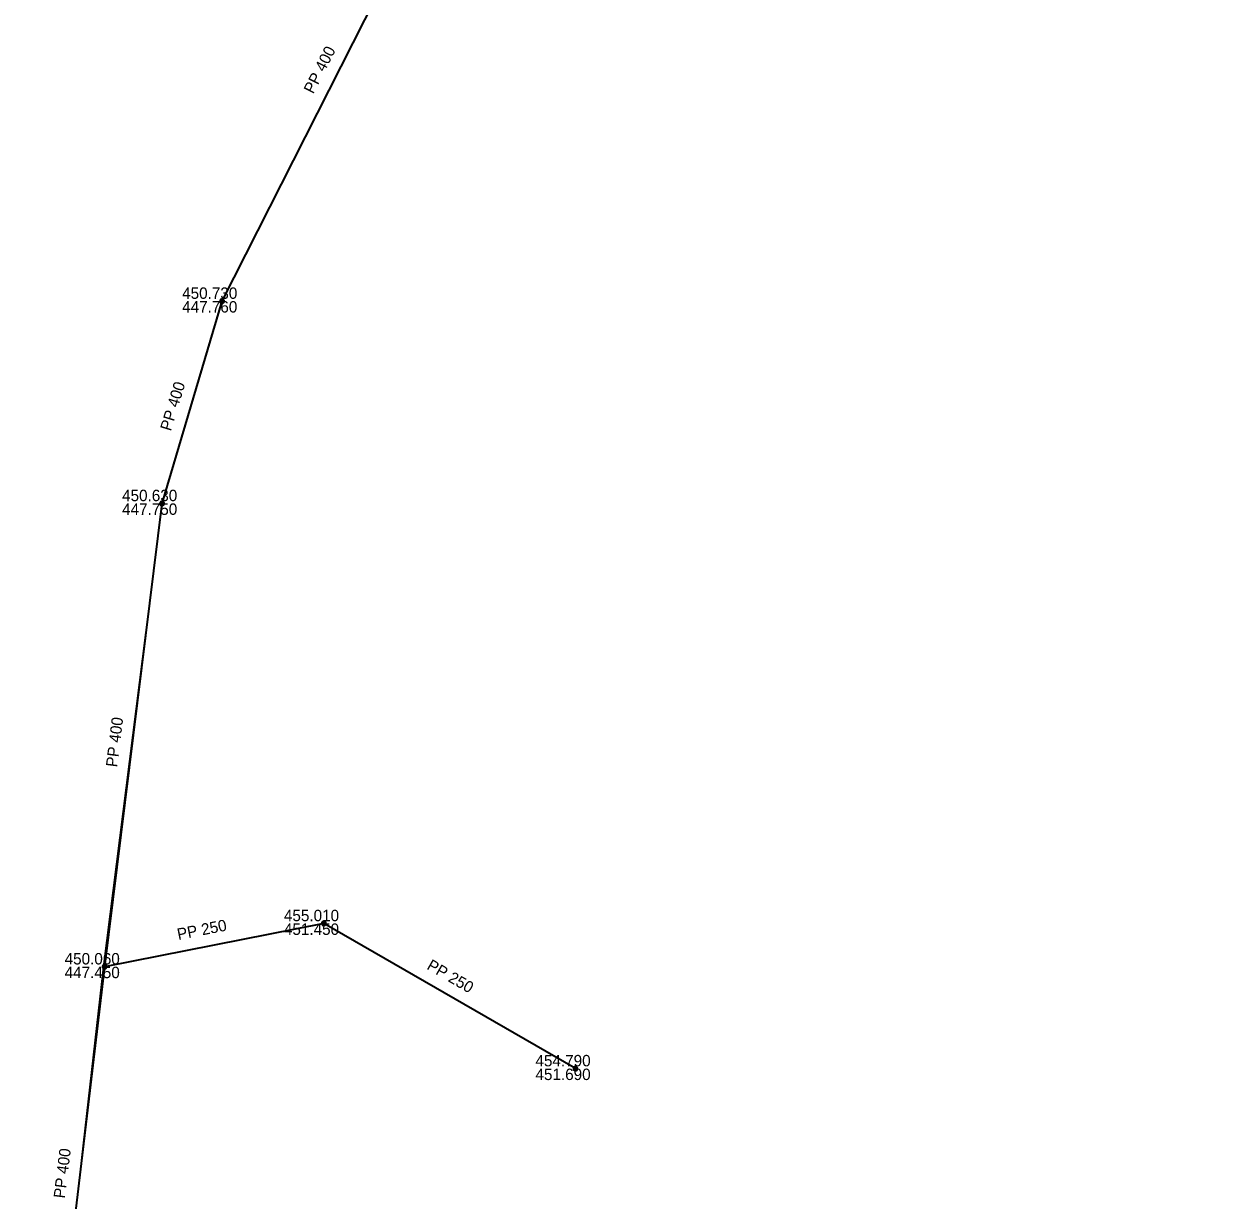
# Model space of a CAD drawing. Extents: x -873619 to -867639, y -1015082 to -1012326.
# Drawn here: x -873192.3 to -873076.9, y -1014089.5 to -1013976.1 of the extents above; entities that cross this region are included whole.
import ezdxf

# ---------------------------------------------------------------- set-up
doc = ezdxf.new("R2010")
doc.units = 0
doc.header["$LTSCALE"] = 0.44
for name, color, linetype, lineweight in [('1', 7, 'Continuous', 13), ('21', 7, 'Continuous', 35), ('3', 7, 'Continuous', 25), ('32', 7, 'Continuous', 13)]:
    doc.layers.add(name, color=color, linetype=linetype, lineweight=lineweight)

msp = doc.modelspace()

# ---------------------------------------------------------------- linework, layer by layer
at = {"layer": '21'}
for p, q in [((-873150.59, -1013958.19), (-873173.22, -1014002.85)), ((-873173.22, -1014002.85), (-873179.01, -1014022.35)), ((-873179.01, -1014022.35), (-873184.55, -1014067)), ((-873163.4, -1014062.83), (-873184.538, -1014067)), ((-873139.15, -1014076.82), (-873163.4, -1014062.83)), ((-873184.55, -1014067), (-873189.13, -1014105.45))]:
    msp.add_line(p, q, dxfattribs=at)
at = {"layer": '3'}
msp.add_lwpolyline([(-873209.421, -1014292.661), (-873208.998, -1014240.45), (-873211.448, -1014197.31), (-873215.58, -1014166.03), (-873205.44, -1014160.07), (-873195.92, -1014151.84), (-873190.998, -1014149.15), (-873189.02, -1014105.45), (-873184.64, -1014067), (-873178.998, -1014022.35), (-873173.208, -1014002.85), (-873150.578, -1013958.19), (-873123.56, -1013906.71), (-873116.49, -1013857.17), (-873096.298, -1013812.05), (-873076.908, -1013772.84), (-873099.08, -1013724.68), (-873112.568, -1013694.19), (-873154.458, -1013666.63), (-873180.788, -1013644.59), (-873224.641, -1013607.538), (-873251.958, -1013559.37), (-873281.448, -1013506.61), (-873307.717, -1013457.772)], dxfattribs=at)
at = {"layer": '32'}
for points in [[(-873172.978, -1014002.85), (-873172.985, -1014002.798), (-873173.002, -1014002.748), (-873173.031, -1014002.704), (-873173.068, -1014002.667), (-873173.113, -1014002.64), (-873173.163, -1014002.623), (-873173.216, -1014002.619), (-873173.267, -1014002.626), (-873173.316, -1014002.645), (-873173.36, -1014002.674), (-873173.396, -1014002.713), (-873173.422, -1014002.758), (-873173.438, -1014002.809), (-873173.441, -1014002.861), (-873173.433, -1014002.913), (-873173.413, -1014002.962), (-873173.382, -1014003.005), (-873173.343, -1014003.039), (-873173.297, -1014003.065), (-873173.245, -1014003.079), (-873173.193, -1014003.081), (-873173.142, -1014003.071), (-873173.093, -1014003.05), (-873173.051, -1014003.019), (-873173.017, -1014002.978), (-873172.993, -1014002.932), (-873172.98, -1014002.881)], [(-873173.009, -1014002.85), (-873173.015, -1014002.801), (-873173.032, -1014002.755), (-873173.059, -1014002.715), (-873173.097, -1014002.683), (-873173.141, -1014002.661), (-873173.189, -1014002.65), (-873173.238, -1014002.65), (-873173.284, -1014002.663), (-873173.328, -1014002.687), (-873173.364, -1014002.72), (-873173.391, -1014002.761), (-873173.407, -1014002.808), (-873173.411, -1014002.857), (-873173.404, -1014002.905), (-873173.385, -1014002.95), (-873173.355, -1014002.99), (-873173.316, -1014003.021), (-873173.272, -1014003.041), (-873173.225, -1014003.051), (-873173.176, -1014003.049), (-873173.129, -1014003.034), (-873173.086, -1014003.009), (-873173.051, -1014002.975), (-873173.026, -1014002.933), (-873173.012, -1014002.886)], [(-873173.039, -1014002.85), (-873173.044, -1014002.805), (-873173.061, -1014002.763), (-873173.09, -1014002.728), (-873173.125, -1014002.701), (-873173.168, -1014002.684), (-873173.213, -1014002.679), (-873173.257, -1014002.685), (-873173.299, -1014002.704), (-873173.333, -1014002.732), (-873173.36, -1014002.769), (-873173.377, -1014002.811), (-873173.38, -1014002.856), (-873173.374, -1014002.901), (-873173.355, -1014002.942), (-873173.326, -1014002.976), (-873173.289, -1014003.002), (-873173.245, -1014003.018), (-873173.201, -1014003.021), (-873173.156, -1014003.013), (-873173.115, -1014002.993), (-873173.081, -1014002.964), (-873173.056, -1014002.926), (-873173.042, -1014002.883)], [(-873173.069, -1014002.85), (-873173.073, -1014002.809), (-873173.092, -1014002.772), (-873173.119, -1014002.741), (-873173.154, -1014002.72), (-873173.194, -1014002.709), (-873173.235, -1014002.711), (-873173.274, -1014002.724), (-873173.308, -1014002.748), (-873173.333, -1014002.78), (-873173.348, -1014002.818), (-873173.35, -1014002.859), (-873173.343, -1014002.899), (-873173.323, -1014002.935), (-873173.294, -1014002.964), (-873173.257, -1014002.983), (-873173.217, -1014002.991), (-873173.176, -1014002.987), (-873173.137, -1014002.972), (-873173.105, -1014002.946), (-873173.083, -1014002.912), (-873173.07, -1014002.873)], [(-873173.098, -1014002.85), (-873173.103, -1014002.814), (-873173.122, -1014002.782), (-873173.147, -1014002.757), (-873173.181, -1014002.742), (-873173.218, -1014002.739), (-873173.252, -1014002.747), (-873173.284, -1014002.767), (-873173.306, -1014002.795), (-873173.32, -1014002.829), (-873173.32, -1014002.866), (-873173.309, -1014002.901), (-873173.288, -1014002.93), (-873173.257, -1014002.951), (-873173.223, -1014002.961), (-873173.186, -1014002.959), (-873173.152, -1014002.945), (-873173.125, -1014002.922), (-873173.105, -1014002.89), (-873173.098, -1014002.855)], [(-873173.129, -1014002.85), (-873173.134, -1014002.819), (-873173.151, -1014002.793), (-873173.176, -1014002.776), (-873173.206, -1014002.769), (-873173.238, -1014002.773), (-873173.265, -1014002.79), (-873173.282, -1014002.814), (-873173.291, -1014002.845), (-873173.287, -1014002.875), (-873173.272, -1014002.903), (-873173.247, -1014002.922), (-873173.218, -1014002.931), (-873173.186, -1014002.928), (-873173.159, -1014002.914), (-873173.139, -1014002.89), (-873173.129, -1014002.861)], [(-873173.159, -1014002.85), (-873173.164, -1014002.826), (-873173.181, -1014002.808), (-873173.203, -1014002.799), (-873173.228, -1014002.802), (-873173.249, -1014002.816), (-873173.26, -1014002.838), (-873173.26, -1014002.863), (-873173.247, -1014002.884), (-873173.228, -1014002.898), (-873173.203, -1014002.901), (-873173.179, -1014002.892), (-873173.164, -1014002.874)], [(-873173.189, -1014002.85), (-873173.194, -1014002.835), (-873173.208, -1014002.829), (-873173.223, -1014002.833), (-873173.23, -1014002.847), (-873173.227, -1014002.862), (-873173.213, -1014002.871), (-873173.198, -1014002.868), (-873173.189, -1014002.856)], [(-873178.769, -1014022.35), (-873178.775, -1014022.298), (-873178.792, -1014022.248), (-873178.821, -1014022.204), (-873178.858, -1014022.167), (-873178.903, -1014022.14), (-873178.953, -1014022.123), (-873179.006, -1014022.119), (-873179.058, -1014022.126), (-873179.107, -1014022.145), (-873179.15, -1014022.174), (-873179.186, -1014022.213), (-873179.212, -1014022.258), (-873179.228, -1014022.309), (-873179.231, -1014022.361), (-873179.223, -1014022.413), (-873179.203, -1014022.462), (-873179.172, -1014022.505), (-873179.133, -1014022.539), (-873179.087, -1014022.565), (-873179.036, -1014022.579), (-873178.983, -1014022.581), (-873178.932, -1014022.571), (-873178.884, -1014022.55), (-873178.841, -1014022.519), (-873178.807, -1014022.478), (-873178.783, -1014022.432), (-873178.771, -1014022.381)], [(-873178.799, -1014022.35), (-873178.805, -1014022.301), (-873178.822, -1014022.255), (-873178.85, -1014022.215), (-873178.887, -1014022.183), (-873178.931, -1014022.161), (-873178.979, -1014022.15), (-873179.028, -1014022.15), (-873179.075, -1014022.163), (-873179.118, -1014022.187), (-873179.154, -1014022.22), (-873179.181, -1014022.261), (-873179.197, -1014022.308), (-873179.201, -1014022.357), (-873179.194, -1014022.405), (-873179.175, -1014022.45), (-873179.145, -1014022.49), (-873179.107, -1014022.521), (-873179.063, -1014022.541), (-873179.015, -1014022.551), (-873178.966, -1014022.549), (-873178.919, -1014022.534), (-873178.876, -1014022.509), (-873178.842, -1014022.475), (-873178.816, -1014022.433), (-873178.802, -1014022.386)], [(-873178.829, -1014022.35), (-873178.835, -1014022.305), (-873178.852, -1014022.263), (-873178.88, -1014022.228), (-873178.916, -1014022.201), (-873178.958, -1014022.184), (-873179.003, -1014022.179), (-873179.048, -1014022.185), (-873179.089, -1014022.204), (-873179.124, -1014022.232), (-873179.151, -1014022.269), (-873179.167, -1014022.311), (-873179.171, -1014022.356), (-873179.164, -1014022.401), (-873179.145, -1014022.442), (-873179.116, -1014022.476), (-873179.079, -1014022.502), (-873179.036, -1014022.518), (-873178.991, -1014022.521), (-873178.946, -1014022.513), (-873178.906, -1014022.493), (-873178.872, -1014022.464), (-873178.846, -1014022.426), (-873178.832, -1014022.383)], [(-873178.859, -1014022.35), (-873178.864, -1014022.309), (-873178.882, -1014022.272), (-873178.909, -1014022.241), (-873178.944, -1014022.22), (-873178.984, -1014022.209), (-873179.025, -1014022.211), (-873179.064, -1014022.224), (-873179.098, -1014022.248), (-873179.123, -1014022.28), (-873179.138, -1014022.318), (-873179.141, -1014022.359), (-873179.133, -1014022.399), (-873179.113, -1014022.435), (-873179.084, -1014022.464), (-873179.047, -1014022.483), (-873179.007, -1014022.491), (-873178.966, -1014022.487), (-873178.928, -1014022.472), (-873178.896, -1014022.446), (-873178.873, -1014022.412), (-873178.86, -1014022.373)], [(-873178.889, -1014022.35), (-873178.894, -1014022.314), (-873178.912, -1014022.282), (-873178.938, -1014022.257), (-873178.972, -1014022.242), (-873179.008, -1014022.239), (-873179.043, -1014022.247), (-873179.074, -1014022.267), (-873179.097, -1014022.295), (-873179.11, -1014022.329), (-873179.11, -1014022.366), (-873179.099, -1014022.401), (-873179.078, -1014022.43), (-873179.048, -1014022.451), (-873179.013, -1014022.461), (-873178.976, -1014022.459), (-873178.942, -1014022.445), (-873178.915, -1014022.422), (-873178.896, -1014022.39), (-873178.889, -1014022.355)], [(-873178.919, -1014022.35), (-873178.924, -1014022.319), (-873178.941, -1014022.293), (-873178.967, -1014022.276), (-873178.997, -1014022.269), (-873179.028, -1014022.273), (-873179.055, -1014022.29), (-873179.073, -1014022.314), (-873179.081, -1014022.345), (-873179.077, -1014022.375), (-873179.062, -1014022.403), (-873179.038, -1014022.422), (-873179.008, -1014022.431), (-873178.977, -1014022.428), (-873178.949, -1014022.414), (-873178.929, -1014022.39), (-873178.919, -1014022.361)], [(-873178.949, -1014022.35), (-873178.954, -1014022.326), (-873178.971, -1014022.308), (-873178.994, -1014022.299), (-873179.018, -1014022.302), (-873179.039, -1014022.316), (-873179.05, -1014022.338), (-873179.05, -1014022.363), (-873179.038, -1014022.384), (-873179.018, -1014022.398), (-873178.993, -1014022.401), (-873178.97, -1014022.392), (-873178.954, -1014022.374)], [(-873178.979, -1014022.35), (-873178.984, -1014022.335), (-873178.999, -1014022.329), (-873179.014, -1014022.333), (-873179.021, -1014022.347), (-873179.017, -1014022.362), (-873179.004, -1014022.371), (-873178.989, -1014022.368), (-873178.979, -1014022.356)], [(-873163.169, -1014062.83), (-873163.175, -1014062.778), (-873163.192, -1014062.728), (-873163.221, -1014062.684), (-873163.258, -1014062.647), (-873163.303, -1014062.62), (-873163.353, -1014062.603), (-873163.406, -1014062.599), (-873163.458, -1014062.606), (-873163.507, -1014062.625), (-873163.55, -1014062.654), (-873163.586, -1014062.693), (-873163.612, -1014062.738), (-873163.628, -1014062.789), (-873163.631, -1014062.841), (-873163.623, -1014062.893), (-873163.603, -1014062.942), (-873163.572, -1014062.985), (-873163.533, -1014063.019), (-873163.487, -1014063.045), (-873163.436, -1014063.059), (-873163.383, -1014063.061), (-873163.332, -1014063.051), (-873163.284, -1014063.03), (-873163.241, -1014062.999), (-873163.207, -1014062.958), (-873163.183, -1014062.912), (-873163.171, -1014062.861)], [(-873163.199, -1014062.83), (-873163.205, -1014062.781), (-873163.222, -1014062.735), (-873163.25, -1014062.695), (-873163.287, -1014062.663), (-873163.331, -1014062.641), (-873163.379, -1014062.63), (-873163.428, -1014062.63), (-873163.475, -1014062.643), (-873163.518, -1014062.667), (-873163.554, -1014062.7), (-873163.581, -1014062.741), (-873163.597, -1014062.788), (-873163.601, -1014062.837), (-873163.594, -1014062.885), (-873163.575, -1014062.93), (-873163.545, -1014062.97), (-873163.507, -1014063.001), (-873163.463, -1014063.021), (-873163.415, -1014063.031), (-873163.366, -1014063.029), (-873163.319, -1014063.014), (-873163.276, -1014062.989), (-873163.242, -1014062.955), (-873163.216, -1014062.913), (-873163.202, -1014062.866)], [(-873163.229, -1014062.83), (-873163.235, -1014062.785), (-873163.252, -1014062.743), (-873163.28, -1014062.708), (-873163.316, -1014062.681), (-873163.358, -1014062.664), (-873163.403, -1014062.659), (-873163.448, -1014062.665), (-873163.489, -1014062.684), (-873163.524, -1014062.712), (-873163.551, -1014062.749), (-873163.567, -1014062.791), (-873163.571, -1014062.836), (-873163.564, -1014062.881), (-873163.545, -1014062.922), (-873163.516, -1014062.956), (-873163.479, -1014062.982), (-873163.436, -1014062.998), (-873163.391, -1014063.001), (-873163.346, -1014062.993), (-873163.306, -1014062.973), (-873163.272, -1014062.944), (-873163.246, -1014062.906), (-873163.232, -1014062.863)], [(-873163.259, -1014062.83), (-873163.264, -1014062.789), (-873163.282, -1014062.752), (-873163.309, -1014062.721), (-873163.344, -1014062.7), (-873163.384, -1014062.689), (-873163.425, -1014062.691), (-873163.464, -1014062.704), (-873163.498, -1014062.728), (-873163.523, -1014062.76), (-873163.538, -1014062.798), (-873163.541, -1014062.839), (-873163.533, -1014062.879), (-873163.513, -1014062.915), (-873163.484, -1014062.944), (-873163.447, -1014062.963), (-873163.407, -1014062.971), (-873163.366, -1014062.967), (-873163.328, -1014062.952), (-873163.296, -1014062.926), (-873163.273, -1014062.892), (-873163.26, -1014062.853)], [(-873163.289, -1014062.83), (-873163.294, -1014062.794), (-873163.312, -1014062.762), (-873163.338, -1014062.737), (-873163.372, -1014062.722), (-873163.408, -1014062.719), (-873163.443, -1014062.727), (-873163.474, -1014062.747), (-873163.497, -1014062.775), (-873163.51, -1014062.809), (-873163.51, -1014062.846), (-873163.499, -1014062.881), (-873163.478, -1014062.91), (-873163.448, -1014062.931), (-873163.413, -1014062.941), (-873163.376, -1014062.939), (-873163.342, -1014062.925), (-873163.315, -1014062.902), (-873163.296, -1014062.87), (-873163.289, -1014062.835)], [(-873163.319, -1014062.83), (-873163.324, -1014062.799), (-873163.341, -1014062.773), (-873163.367, -1014062.756), (-873163.397, -1014062.749), (-873163.428, -1014062.753), (-873163.455, -1014062.77), (-873163.473, -1014062.794), (-873163.481, -1014062.825), (-873163.477, -1014062.855), (-873163.462, -1014062.883), (-873163.438, -1014062.902), (-873163.408, -1014062.911), (-873163.377, -1014062.908), (-873163.349, -1014062.894), (-873163.329, -1014062.87), (-873163.319, -1014062.841)], [(-873163.349, -1014062.83), (-873163.354, -1014062.806), (-873163.371, -1014062.788), (-873163.394, -1014062.779), (-873163.418, -1014062.782), (-873163.439, -1014062.796), (-873163.45, -1014062.818), (-873163.45, -1014062.843), (-873163.438, -1014062.864), (-873163.418, -1014062.878), (-873163.393, -1014062.881), (-873163.37, -1014062.872), (-873163.354, -1014062.854)], [(-873163.379, -1014062.83), (-873163.384, -1014062.815), (-873163.399, -1014062.809), (-873163.414, -1014062.813), (-873163.421, -1014062.827), (-873163.417, -1014062.842), (-873163.404, -1014062.851), (-873163.389, -1014062.848), (-873163.379, -1014062.836)], [(-873184.309, -1014067), (-873184.315, -1014066.948), (-873184.332, -1014066.898), (-873184.361, -1014066.854), (-873184.398, -1014066.817), (-873184.443, -1014066.79), (-873184.493, -1014066.773), (-873184.546, -1014066.769), (-873184.598, -1014066.776), (-873184.647, -1014066.795), (-873184.69, -1014066.824), (-873184.726, -1014066.863), (-873184.752, -1014066.908), (-873184.768, -1014066.959), (-873184.771, -1014067.011), (-873184.763, -1014067.063), (-873184.743, -1014067.112), (-873184.712, -1014067.155), (-873184.673, -1014067.189), (-873184.627, -1014067.215), (-873184.576, -1014067.229), (-873184.523, -1014067.231), (-873184.472, -1014067.221), (-873184.424, -1014067.2), (-873184.381, -1014067.169), (-873184.347, -1014067.128), (-873184.323, -1014067.082), (-873184.311, -1014067.031)], [(-873184.339, -1014067), (-873184.345, -1014066.951), (-873184.362, -1014066.905), (-873184.39, -1014066.865), (-873184.427, -1014066.833), (-873184.471, -1014066.811), (-873184.519, -1014066.8), (-873184.568, -1014066.8), (-873184.615, -1014066.813), (-873184.658, -1014066.837), (-873184.694, -1014066.87), (-873184.721, -1014066.911), (-873184.737, -1014066.958), (-873184.741, -1014067.007), (-873184.734, -1014067.055), (-873184.715, -1014067.1), (-873184.685, -1014067.14), (-873184.647, -1014067.171), (-873184.603, -1014067.191), (-873184.555, -1014067.201), (-873184.506, -1014067.199), (-873184.459, -1014067.184), (-873184.416, -1014067.159), (-873184.382, -1014067.125), (-873184.356, -1014067.083), (-873184.342, -1014067.036)], [(-873184.369, -1014067), (-873184.375, -1014066.955), (-873184.392, -1014066.913), (-873184.42, -1014066.878), (-873184.456, -1014066.851), (-873184.498, -1014066.834), (-873184.543, -1014066.829), (-873184.588, -1014066.835), (-873184.629, -1014066.854), (-873184.664, -1014066.882), (-873184.691, -1014066.919), (-873184.707, -1014066.961), (-873184.711, -1014067.006), (-873184.704, -1014067.051), (-873184.685, -1014067.092), (-873184.656, -1014067.126), (-873184.619, -1014067.152), (-873184.576, -1014067.168), (-873184.531, -1014067.171), (-873184.486, -1014067.163), (-873184.446, -1014067.143), (-873184.412, -1014067.114), (-873184.386, -1014067.076), (-873184.372, -1014067.033)], [(-873184.399, -1014067), (-873184.404, -1014066.959), (-873184.422, -1014066.922), (-873184.449, -1014066.891), (-873184.484, -1014066.87), (-873184.524, -1014066.859), (-873184.565, -1014066.861), (-873184.604, -1014066.874), (-873184.638, -1014066.898), (-873184.663, -1014066.93), (-873184.678, -1014066.968), (-873184.681, -1014067.009), (-873184.673, -1014067.049), (-873184.653, -1014067.085), (-873184.624, -1014067.114), (-873184.587, -1014067.133), (-873184.547, -1014067.141), (-873184.506, -1014067.137), (-873184.468, -1014067.122), (-873184.436, -1014067.096), (-873184.413, -1014067.062), (-873184.4, -1014067.023)], [(-873184.429, -1014067), (-873184.434, -1014066.964), (-873184.452, -1014066.932), (-873184.478, -1014066.907), (-873184.512, -1014066.892), (-873184.548, -1014066.889), (-873184.583, -1014066.897), (-873184.614, -1014066.917), (-873184.637, -1014066.945), (-873184.65, -1014066.979), (-873184.65, -1014067.016), (-873184.639, -1014067.051), (-873184.618, -1014067.08), (-873184.588, -1014067.101), (-873184.553, -1014067.111), (-873184.516, -1014067.109), (-873184.482, -1014067.095), (-873184.455, -1014067.072), (-873184.436, -1014067.04), (-873184.429, -1014067.005)], [(-873184.459, -1014067), (-873184.464, -1014066.969), (-873184.481, -1014066.943), (-873184.507, -1014066.926), (-873184.537, -1014066.919), (-873184.568, -1014066.923), (-873184.595, -1014066.94), (-873184.613, -1014066.964), (-873184.621, -1014066.995), (-873184.617, -1014067.025), (-873184.602, -1014067.053), (-873184.578, -1014067.072), (-873184.548, -1014067.081), (-873184.517, -1014067.078), (-873184.489, -1014067.064), (-873184.469, -1014067.04), (-873184.459, -1014067.011)], [(-873184.489, -1014067), (-873184.494, -1014066.976), (-873184.511, -1014066.958), (-873184.534, -1014066.949), (-873184.558, -1014066.952), (-873184.579, -1014066.966), (-873184.59, -1014066.988), (-873184.59, -1014067.013), (-873184.578, -1014067.034), (-873184.558, -1014067.048), (-873184.533, -1014067.051), (-873184.51, -1014067.042), (-873184.494, -1014067.024)], [(-873184.519, -1014067), (-873184.524, -1014066.985), (-873184.539, -1014066.979), (-873184.554, -1014066.983), (-873184.561, -1014066.997), (-873184.557, -1014067.012), (-873184.544, -1014067.021), (-873184.529, -1014067.018), (-873184.519, -1014067.006)], [(-873138.919, -1014076.82), (-873138.925, -1014076.768), (-873138.942, -1014076.718), (-873138.971, -1014076.674), (-873139.008, -1014076.637), (-873139.053, -1014076.61), (-873139.103, -1014076.593), (-873139.156, -1014076.589), (-873139.208, -1014076.596), (-873139.257, -1014076.615), (-873139.3, -1014076.644), (-873139.336, -1014076.683), (-873139.362, -1014076.728), (-873139.378, -1014076.779), (-873139.381, -1014076.831), (-873139.373, -1014076.883), (-873139.353, -1014076.932), (-873139.322, -1014076.975), (-873139.283, -1014077.009), (-873139.237, -1014077.035), (-873139.186, -1014077.049), (-873139.133, -1014077.051), (-873139.082, -1014077.041), (-873139.034, -1014077.02), (-873138.991, -1014076.989), (-873138.957, -1014076.948), (-873138.933, -1014076.902), (-873138.921, -1014076.851)], [(-873138.949, -1014076.82), (-873138.955, -1014076.771), (-873138.972, -1014076.725), (-873139, -1014076.685), (-873139.037, -1014076.653), (-873139.081, -1014076.631), (-873139.129, -1014076.62), (-873139.178, -1014076.62), (-873139.225, -1014076.633), (-873139.268, -1014076.657), (-873139.304, -1014076.69), (-873139.331, -1014076.731), (-873139.347, -1014076.778), (-873139.351, -1014076.827), (-873139.344, -1014076.875), (-873139.325, -1014076.92), (-873139.295, -1014076.96), (-873139.257, -1014076.991), (-873139.213, -1014077.011), (-873139.165, -1014077.021), (-873139.116, -1014077.019), (-873139.069, -1014077.004), (-873139.026, -1014076.979), (-873138.992, -1014076.945), (-873138.966, -1014076.903), (-873138.952, -1014076.856)], [(-873138.979, -1014076.82), (-873138.985, -1014076.775), (-873139.002, -1014076.733), (-873139.03, -1014076.698), (-873139.066, -1014076.671), (-873139.108, -1014076.654), (-873139.153, -1014076.649), (-873139.198, -1014076.655), (-873139.239, -1014076.674), (-873139.274, -1014076.702), (-873139.301, -1014076.739), (-873139.317, -1014076.781), (-873139.321, -1014076.826), (-873139.314, -1014076.871), (-873139.295, -1014076.912), (-873139.266, -1014076.946), (-873139.229, -1014076.972), (-873139.186, -1014076.988), (-873139.141, -1014076.991), (-873139.096, -1014076.983), (-873139.056, -1014076.963), (-873139.022, -1014076.934), (-873138.996, -1014076.896), (-873138.982, -1014076.853)], [(-873139.009, -1014076.82), (-873139.014, -1014076.779), (-873139.032, -1014076.742), (-873139.059, -1014076.711), (-873139.094, -1014076.69), (-873139.134, -1014076.679), (-873139.175, -1014076.681), (-873139.214, -1014076.694), (-873139.248, -1014076.718), (-873139.273, -1014076.75), (-873139.288, -1014076.788), (-873139.291, -1014076.829), (-873139.283, -1014076.869), (-873139.263, -1014076.905), (-873139.234, -1014076.934), (-873139.197, -1014076.953), (-873139.157, -1014076.961), (-873139.116, -1014076.957), (-873139.078, -1014076.942), (-873139.046, -1014076.916), (-873139.023, -1014076.882), (-873139.01, -1014076.843)], [(-873139.039, -1014076.82), (-873139.044, -1014076.784), (-873139.062, -1014076.752), (-873139.088, -1014076.727), (-873139.122, -1014076.712), (-873139.158, -1014076.709), (-873139.193, -1014076.717), (-873139.224, -1014076.737), (-873139.247, -1014076.765), (-873139.26, -1014076.799), (-873139.26, -1014076.836), (-873139.249, -1014076.871), (-873139.228, -1014076.9), (-873139.198, -1014076.921), (-873139.163, -1014076.931), (-873139.126, -1014076.929), (-873139.092, -1014076.915), (-873139.065, -1014076.892), (-873139.046, -1014076.86), (-873139.039, -1014076.825)], [(-873139.069, -1014076.82), (-873139.074, -1014076.789), (-873139.091, -1014076.763), (-873139.117, -1014076.746), (-873139.147, -1014076.739), (-873139.178, -1014076.743), (-873139.205, -1014076.76), (-873139.223, -1014076.784), (-873139.231, -1014076.815), (-873139.227, -1014076.845), (-873139.212, -1014076.873), (-873139.188, -1014076.892), (-873139.158, -1014076.901), (-873139.127, -1014076.898), (-873139.099, -1014076.884), (-873139.079, -1014076.86), (-873139.069, -1014076.831)], [(-873139.099, -1014076.82), (-873139.104, -1014076.796), (-873139.121, -1014076.778), (-873139.144, -1014076.769), (-873139.168, -1014076.772), (-873139.189, -1014076.786), (-873139.2, -1014076.808), (-873139.2, -1014076.833), (-873139.188, -1014076.854), (-873139.168, -1014076.868), (-873139.143, -1014076.871), (-873139.12, -1014076.862), (-873139.104, -1014076.844)], [(-873139.129, -1014076.82), (-873139.134, -1014076.805), (-873139.149, -1014076.799), (-873139.164, -1014076.803), (-873139.171, -1014076.817), (-873139.167, -1014076.832), (-873139.154, -1014076.841), (-873139.139, -1014076.838), (-873139.129, -1014076.826)]]:
    msp.add_lwpolyline(points, close=True, dxfattribs=at)

# ---------------------------------------------------------------- texts
at = {"layer": '1'}
for s, rotation, p in [('PP 400', 63, (-873164.421, -1013982.943)), ('PP 400', 73, (-873178.156, -1014015.436)), ('PP 400', 83, (-873183.327, -1014047.807)), ('PP 250', 11, (-873177.429, -1014064.425)), ('PP 250', 330, (-873153.558, -1014067.179)), ('PP 400', 83, (-873188.372, -1014089.364))]:
    msp.add_text(s, height=1.1, rotation=rotation, dxfattribs=at).set_placement(p)
for s, p in [('450.730 ', (-873177.06, -1014002.63)), ('447.760 ', (-873177.06, -1014003.95)), ('450.630 ', (-873182.85, -1014022.13)), ('447.750 ', (-873182.85, -1014023.45)), ('455.010 ', (-873167.25, -1014062.61)), ('451.450 ', (-873167.25, -1014063.93)), ('450.060 ', (-873188.39, -1014066.78)), ('447.450 ', (-873188.39, -1014068.1)), ('454.790 ', (-873143, -1014076.6)), ('451.690 ', (-873143, -1014077.92))]:
    msp.add_text(s, height=1.1, dxfattribs=at).set_placement(p)

doc.saveas('drawing.dxf')
